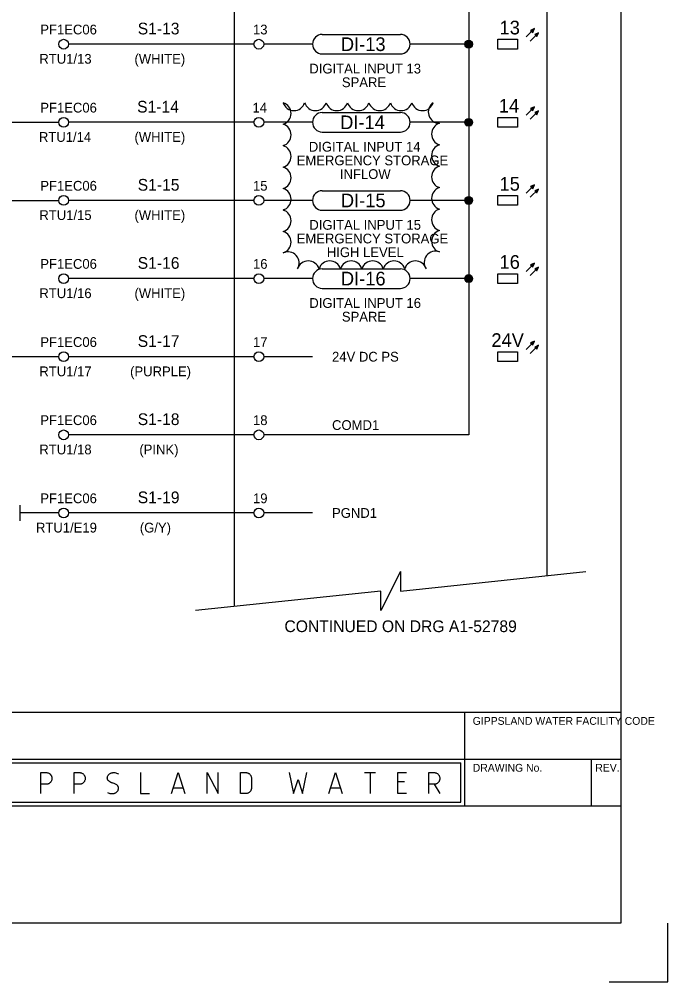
# Model space of a CAD drawing. Extents: x 0 to 841, y 0 to 594.
# Drawn here: x 674.9 to 841, y 0 to 246.4 of the extents above; entities that cross this region are included whole.
import ezdxf

# ---------------------------------------------------------------- set-up
doc = ezdxf.new("R2010")
doc.units = 0
for name, color, linetype in [('A1BORDER', 7, 'Continuous'), ('Level 1', 7, 'Continuous'), ('Level 10', 7, 'Continuous')]:
    doc.layers.add(name, color=color, linetype=linetype)

msp = doc.modelspace()

# ---------------------------------------------------------------- linework, layer by layer
at = {"layer": 'A1BORDER'}
for p, q in [((829, 581), (829, 15)), ((592.5, 69), (829, 69)), ((789, 45), (789, 69)), ((28, 57), (829, 57)), ((821.5, 45), (821.5, 57)), ((637, 56), (788, 56)), ((788, 46), (788, 56)), ((663, 46), (788, 46)), ((664, 45), (829, 45)), ((829, 15), (28, 15)), ((829, 15), (829, 15)), ((841, 0), (841, 15)), ((826, 0), (841, 0))]:
    msp.add_line(p, q, dxfattribs=at)
for points in [[(680.42, 48.16), (680.42, 53.54), (681.84, 53.54), (681.96, 53.54), (682.08, 53.52), (682.2, 53.49), (682.32, 53.45), (682.43, 53.4), (682.54, 53.34), (682.65, 53.27), (682.74, 53.19), (682.84, 53.1), (682.92, 53), (682.99, 52.9), (683.06, 52.79), (683.12, 52.67), (683.17, 52.56), (683.21, 52.43), (683.23, 52.31), (683.25, 52.18), (683.26, 52.05), (683.25, 51.91), (683.23, 51.78), (683.21, 51.66), (683.17, 51.53), (683.12, 51.42), (683.06, 51.3), (682.99, 51.19), (682.92, 51.09), (682.84, 50.99), (682.74, 50.9), (682.65, 50.82), (682.54, 50.75), (682.43, 50.69), (682.32, 50.64), (682.2, 50.6), (682.08, 50.57), (681.96, 50.55), (681.84, 50.55), (680.42, 50.55)], [(688.93, 48.16), (688.93, 53.54), (690.35, 53.54), (690.47, 53.54), (690.59, 53.52), (690.71, 53.49), (690.83, 53.45), (690.94, 53.4), (691.05, 53.34), (691.16, 53.27), (691.26, 53.19), (691.35, 53.1), (691.43, 53), (691.51, 52.9), (691.57, 52.79), (691.63, 52.67), (691.68, 52.56), (691.72, 52.43), (691.75, 52.31), (691.76, 52.18), (691.77, 52.05), (691.76, 51.91), (691.75, 51.78), (691.72, 51.66), (691.68, 51.53), (691.63, 51.42), (691.57, 51.3), (691.51, 51.19), (691.43, 51.09), (691.35, 50.99), (691.26, 50.9), (691.16, 50.82), (691.05, 50.75), (690.94, 50.69), (690.83, 50.64), (690.71, 50.6), (690.59, 50.57), (690.47, 50.55), (690.35, 50.55), (688.93, 50.55)], [(697.45, 48.46), (697.67, 48.36), (697.9, 48.27), (698.12, 48.21), (698.36, 48.17), (698.6, 48.16), (698.84, 48.16), (698.87, 48.16), (699.03, 48.18), (699.18, 48.21), (699.33, 48.26), (699.48, 48.32), (699.62, 48.4), (699.72, 48.46), (699.81, 48.53), (699.9, 48.61), (699.98, 48.69), (700.05, 48.78), (700.11, 48.88), (700.17, 48.99), (700.22, 49.09), (700.25, 49.21), (700.28, 49.32), (700.29, 49.36), (700.3, 49.44), (700.3, 49.52), (700.3, 49.61), (700.29, 49.69), (700.27, 49.77), (700.25, 49.86), (700.22, 49.93), (700.18, 50.01), (700.14, 50.09), (700.09, 50.15), (700.04, 50.21), (700.01, 50.25), (699.85, 50.39), (699.69, 50.51), (699.52, 50.61), (699.34, 50.7), (699.15, 50.78), (698.95, 50.83), (698.87, 50.85), (698.68, 50.9), (698.49, 50.96), (698.3, 51.04), (698.12, 51.14), (697.96, 51.26), (697.8, 51.39), (697.73, 51.45), (697.67, 51.51), (697.62, 51.57), (697.58, 51.64), (697.53, 51.71), (697.5, 51.79), (697.47, 51.87), (697.46, 51.95), (697.44, 52.04), (697.43, 52.12), (697.43, 52.21), (697.44, 52.29), (697.45, 52.35), (697.47, 52.46), (697.51, 52.58), (697.55, 52.69), (697.61, 52.79), (697.67, 52.89), (697.74, 52.99), (697.82, 53.07), (697.9, 53.15), (697.99, 53.23), (698.02, 53.24), (698.15, 53.33), (698.3, 53.4), (698.44, 53.45), (698.6, 53.5), (698.75, 53.52), (698.87, 53.54), (699.11, 53.55), (699.35, 53.53), (699.58, 53.49), (699.82, 53.43), (700.04, 53.35), (700.27, 53.25)], [(705.96, 53.54), (705.96, 48.16), (708.23, 48.16)], [(713.91, 48.16), (715.61, 53.54), (717.32, 48.16)], [(722.99, 48.16), (722.99, 53.54), (725.83, 48.16), (725.83, 53.54)], [(731.52, 48.16), (731.52, 53.54), (732.94, 53.54), (733.06, 53.54), (733.18, 53.52), (733.3, 53.49), (733.42, 53.45), (733.53, 53.4), (733.64, 53.34), (733.75, 53.27), (733.84, 53.19), (733.94, 53.1), (734.02, 53), (734.09, 52.9), (734.16, 52.79), (734.22, 52.67), (734.27, 52.56), (734.31, 52.43), (734.33, 52.31), (734.35, 52.18), (734.36, 52.05), (734.36, 49.66), (734.35, 49.52), (734.33, 49.39), (734.31, 49.27), (734.27, 49.14), (734.22, 49.02), (734.16, 48.91), (734.09, 48.8), (734.02, 48.7), (733.94, 48.6), (733.84, 48.51), (733.75, 48.43), (733.64, 48.36), (733.53, 48.3), (733.42, 48.25), (733.3, 48.21), (733.18, 48.18), (733.06, 48.16), (732.94, 48.16), (731.52, 48.16)], [(744.01, 53.54), (745.14, 48.16), (746.28, 51.75), (747.41, 48.16), (748.55, 53.54)], [(754.22, 48.16), (755.92, 53.54), (757.63, 48.16)], [(763.31, 53.54), (766.15, 53.54)], [(764.73, 53.54), (764.73, 48.16)], [(774.09, 48.16), (771.82, 48.16), (771.82, 53.54), (774.09, 53.54)], [(779.78, 48.16), (779.78, 53.54), (781.2, 53.54), (781.32, 53.54), (781.44, 53.52), (781.56, 53.49), (781.68, 53.45), (781.79, 53.4), (781.9, 53.34), (782.01, 53.27), (782.1, 53.19), (782.2, 53.1), (782.28, 53), (782.35, 52.9), (782.42, 52.79), (782.48, 52.67), (782.53, 52.56), (782.56, 52.43), (782.59, 52.31), (782.61, 52.18), (782.61, 52.05), (782.61, 51.91), (782.59, 51.78), (782.56, 51.66), (782.53, 51.53), (782.48, 51.42), (782.42, 51.3), (782.35, 51.19), (782.28, 51.09), (782.2, 50.99), (782.1, 50.9), (782.01, 50.82), (781.9, 50.75), (781.79, 50.69), (781.68, 50.64), (781.56, 50.6), (781.44, 50.57), (781.32, 50.55), (781.2, 50.55), (779.78, 50.55)], [(714.48, 49.66), (716.75, 49.66)], [(754.79, 49.66), (757.06, 49.66)], [(773.53, 51.15), (771.82, 51.15)], [(781.2, 50.55), (782.61, 48.16)]]:
    msp.add_lwpolyline(points, dxfattribs=at)
at = {"layer": 'Level 1'}
for p, q in [((790, 480), (790, 140)), ((752.5, 242.5), (772.5, 242.5)), ((735, 240), (687.5, 240)), ((750, 240), (737.5, 240)), ((790, 240), (775, 240)), ((752.5, 237.5), (772.5, 237.5)), ((752.5, 222.5), (772.5, 222.5)), ((280, 220), (685, 220)), ((735, 220), (687.5, 220)), ((750, 220), (737.5, 220)), ((790, 220), (775, 220)), ((752.5, 217.5), (772.5, 217.5)), ((752.5, 202.5), (772.5, 202.5)), ((280, 200), (685, 200)), ((735, 200), (687.5, 200)), ((750, 200), (737.5, 200)), ((790, 200), (775, 200)), ((752.5, 197.5), (772.5, 197.5)), ((752.5, 182.5), (772.5, 182.5)), ((735, 180), (687.5, 180)), ((750, 180), (737.5, 180)), ((790, 180), (775, 180)), ((752.5, 177.5), (772.5, 177.5)), ((685, 160), (630, 160)), ((735, 160), (687.5, 160)), ((750, 160), (737.5, 160)), ((735, 140), (687.5, 140)), ((790, 140), (737.5, 140)), ((685, 120), (675, 120)), ((735, 120), (687.5, 120)), ((750, 120), (737.5, 120)), ((772.5, 105), (767.5, 95)), ((772.5, 105), (772.5, 100)), ((772.5, 100), (820, 105)), ((767.5, 100), (720, 95)), ((767.5, 95), (767.5, 100))]:
    msp.add_line(p, q, dxfattribs=at)
msp.add_lwpolyline([(730, 96.05), (730, 560), (810, 560), (810, 103.95)], dxfattribs=at)
for points in [[(797.5, 241.25), (802.5, 241.25), (802.5, 238.75), (797.5, 238.75)], [(797.5, 221.25), (802.5, 221.25), (802.5, 218.75), (797.5, 218.75)], [(797.5, 201.25), (802.5, 201.25), (802.5, 198.75), (797.5, 198.75)], [(797.5, 181.25), (802.5, 181.25), (802.5, 178.75), (797.5, 178.75)], [(797.5, 161.25), (802.5, 161.25), (802.5, 158.75), (797.5, 158.75)]]:
    msp.add_lwpolyline(points, close=True, dxfattribs=at)
for centre, radius, start, end in [((752.5, 240), 2.5, 90, 270), ((772.5, 240), 2.5, 270, 90), ((745.24, 225.87), 2.88, 197.5, 342.5), ((741.63, 222.26), 2.88, 287.5, 72.5), ((750.73, 225.87), 2.88, 197.5, 342.5), ((756.22, 225.87), 2.88, 197.5, 342.5), ((761.71, 225.87), 2.88, 197.5, 342.5), ((767.2, 225.87), 2.88, 197.5, 342.5), ((772.69, 225.87), 2.88, 197.5, 342.5), ((778.18, 225.87), 2.88, 197.5, 342.5), ((782.54, 222.62), 2.88, 124.2101, 269.2101), ((752.5, 220), 2.5, 90, 270), ((772.5, 220), 2.5, 270, 90), ((741.63, 216.77), 2.88, 287.5, 72.5), ((783.37, 217), 2.88, 107.5, 252.5), ((741.63, 211.28), 2.88, 287.5, 72.5), ((783.37, 211.51), 2.88, 107.5, 252.5), ((741.63, 205.79), 2.88, 287.5, 72.5), ((783.37, 206.02), 2.88, 107.5, 252.5), ((741.63, 200.3), 2.88, 287.5, 72.5), ((752.5, 200), 2.5, 90, 270), ((772.5, 200), 2.5, 270, 90), ((783.37, 200.54), 2.88, 107.5, 252.5), ((741.63, 194.81), 2.88, 287.5, 72.5), ((783.37, 195.05), 2.88, 107.5, 252.5), ((783.37, 189.56), 2.88, 107.5, 252.5), ((741.63, 189.32), 2.88, 287.5, 72.5), ((743.69, 183.96), 2.88, 329.5167, 114.5167), ((781.48, 184.12), 2.88, 69.3086, 214.3086), ((748.92, 181.63), 2.88, 17.5, 162.5), ((752.5, 180), 2.5, 90, 270), ((754.41, 181.63), 2.88, 17.5, 162.5), ((759.9, 181.63), 2.88, 17.5, 162.5), ((765.39, 181.63), 2.88, 17.5, 162.5), ((770.87, 181.63), 2.88, 17.5, 162.5), ((772.5, 180), 2.5, 270, 90), ((776.36, 181.63), 2.88, 17.5, 162.5)]:
    msp.add_arc(centre, radius, start, end, dxfattribs=at)
at = {"layer": 'Level 10'}
for p, q in [((804.73, 241.86), (806.86, 243.98)), ((805.79, 240.8), (807.91, 242.92)), ((805.96, 243.58), (806.67, 243.58)), ((806, 243.43), (806.61, 243.43)), ((806.14, 243.28), (806.53, 243.28)), ((806.29, 243.72), (806.74, 243.72)), ((806.3, 243.12), (806.47, 243.12)), ((806.62, 243.88), (806.81, 243.88)), ((807.02, 242.52), (807.73, 242.52)), ((807.06, 242.37), (807.66, 242.37)), ((807.21, 242.22), (807.6, 242.22)), ((807.35, 242.66), (807.8, 242.66)), ((807.36, 242.06), (807.53, 242.06)), ((807.68, 242.81), (807.87, 242.81)), ((789.01, 240.1), (790.99, 240.1)), ((789.02, 239.8), (790.98, 239.8)), ((789.08, 240.4), (790.92, 240.4)), ((789.13, 239.5), (790.87, 239.5)), ((789.29, 240.7), (790.71, 240.7)), ((789.4, 239.2), (790.6, 239.2)), ((790, 241), (790, 241)), ((804.73, 221.86), (806.86, 223.98)), ((805.79, 220.8), (807.91, 222.92)), ((805.96, 223.58), (806.67, 223.58)), ((806, 223.43), (806.61, 223.43)), ((806.14, 223.28), (806.53, 223.28)), ((806.29, 223.72), (806.74, 223.72)), ((806.3, 223.12), (806.47, 223.12)), ((806.62, 223.88), (806.81, 223.88)), ((807.02, 222.52), (807.73, 222.52)), ((807.06, 222.37), (807.66, 222.37)), ((807.21, 222.22), (807.6, 222.22)), ((807.35, 222.66), (807.8, 222.66)), ((807.36, 222.06), (807.53, 222.06)), ((807.68, 222.81), (807.87, 222.81)), ((789.01, 220.1), (790.99, 220.1)), ((789.02, 219.8), (790.98, 219.8)), ((789.08, 220.4), (790.92, 220.4)), ((789.13, 219.5), (790.87, 219.5)), ((789.29, 220.7), (790.71, 220.7)), ((790, 221), (790, 221)), ((789.4, 219.2), (790.6, 219.2)), ((804.73, 201.86), (806.86, 203.98)), ((805.79, 200.8), (807.91, 202.92)), ((805.96, 203.58), (806.67, 203.58)), ((806, 203.43), (806.61, 203.43)), ((806.14, 203.28), (806.53, 203.28)), ((806.29, 203.72), (806.74, 203.72)), ((806.3, 203.12), (806.47, 203.12)), ((806.62, 203.88), (806.81, 203.88)), ((807.02, 202.52), (807.73, 202.52)), ((807.06, 202.37), (807.66, 202.37)), ((807.21, 202.22), (807.6, 202.22)), ((807.35, 202.66), (807.8, 202.66)), ((807.36, 202.06), (807.53, 202.06)), ((807.68, 202.81), (807.87, 202.81)), ((789.01, 200.1), (790.99, 200.1)), ((789.02, 199.8), (790.98, 199.8)), ((789.08, 200.4), (790.92, 200.4)), ((789.29, 200.7), (790.71, 200.7)), ((790, 201), (790, 201)), ((789.13, 199.5), (790.87, 199.5)), ((789.4, 199.2), (790.6, 199.2)), ((804.73, 181.85), (806.86, 183.98)), ((805.79, 180.8), (807.91, 182.92)), ((805.96, 183.58), (806.67, 183.58)), ((806, 183.43), (806.61, 183.43)), ((806.14, 183.28), (806.53, 183.28)), ((806.29, 183.72), (806.74, 183.72)), ((806.3, 183.12), (806.47, 183.12)), ((806.62, 183.88), (806.81, 183.88)), ((807.02, 182.52), (807.73, 182.52)), ((807.06, 182.37), (807.66, 182.37)), ((807.35, 182.66), (807.8, 182.66)), ((807.68, 182.81), (807.87, 182.81)), ((789.01, 180.1), (790.99, 180.1)), ((789.08, 180.4), (790.92, 180.4)), ((789.29, 180.7), (790.71, 180.7)), ((790, 181), (790, 181)), ((807.21, 182.22), (807.6, 182.22)), ((807.36, 182.06), (807.53, 182.06)), ((789.02, 179.8), (790.98, 179.8)), ((789.13, 179.5), (790.87, 179.5)), ((789.4, 179.2), (790.6, 179.2)), ((804.73, 161.85), (806.86, 163.98)), ((805.79, 160.8), (807.91, 162.92)), ((805.96, 163.58), (806.67, 163.58)), ((806, 163.43), (806.61, 163.43)), ((806.14, 163.28), (806.53, 163.28)), ((806.29, 163.72), (806.74, 163.72)), ((806.3, 163.12), (806.47, 163.12)), ((806.62, 163.88), (806.81, 163.88)), ((807.35, 162.66), (807.8, 162.66)), ((807.68, 162.81), (807.87, 162.81)), ((807.02, 162.52), (807.73, 162.52)), ((807.06, 162.37), (807.66, 162.37)), ((807.21, 162.22), (807.6, 162.22)), ((807.36, 162.06), (807.53, 162.06)), ((675, 122), (675, 118))]:
    msp.add_line(p, q, dxfattribs=at)
for points in [[(806.86, 243.98), (805.88, 243.54), (806.41, 243)], [(807.91, 242.92), (806.94, 242.48), (807.48, 241.94)], [(806.86, 223.98), (805.88, 223.54), (806.41, 223)], [(807.91, 222.92), (806.94, 222.48), (807.48, 221.94)], [(806.86, 203.98), (805.88, 203.54), (806.41, 203)], [(807.91, 202.92), (806.94, 202.48), (807.48, 201.94)], [(806.86, 183.98), (805.88, 183.54), (806.41, 183)], [(807.91, 182.92), (806.94, 182.48), (807.48, 181.94)], [(806.86, 163.98), (805.88, 163.54), (806.41, 163)], [(807.91, 162.92), (806.94, 162.48), (807.48, 161.94)]]:
    msp.add_lwpolyline(points, close=True, dxfattribs=at)
for centre, radius in [((686.25, 240), 1.25), ((736.25, 240), 1.25), ((790, 240), 1), ((686.25, 220), 1.25), ((736.25, 220), 1.25), ((790, 220), 1), ((686.25, 200), 1.25), ((736.25, 200), 1.25), ((790, 200), 1), ((686.25, 180), 1.25), ((736.25, 180), 1.25), ((790, 180), 1), ((686.25, 160), 1.25), ((736.25, 160), 1.25), ((686.25, 140), 1.25), ((736.25, 140), 1.25), ((686.25, 120), 1.25), ((736.25, 120), 1.25)]:
    msp.add_circle(centre, radius, dxfattribs=at)

# ---------------------------------------------------------------- texts
at = {"layer": 'A1BORDER'}
for s, p in [('GIPPSLAND WATER FACILITY CODE', (791.03, 65.77)), ('DRAWING No.', (791.03, 53.77)), ('REV.', (822.43, 53.77))]:
    msp.add_text(s, height=2, dxfattribs=at).set_placement(p)
at = {"layer": 'Level 1'}
for s, height, p in [('PF1EC06', 2.5, (680.27, 242.5)), ('S1-13', 3, (705.22, 242.5)), ('13', 2.5, (734.75, 242.5)), ('13', 3.5, (797.91, 242.5)), ('DI-13', 3.5, (757.27, 238.25)), ('RTU1/13', 2.5, (680.03, 235)), ('(WHITE)', 2.5, (704.39, 235)), ('DIGITAL INPUT 13', 2.5, (749.18, 232.5)), ('SPARE', 2.5, (757.52, 229)), ('PF1EC06', 2.5, (680.27, 222.5)), ('S1-14', 3, (705.07, 222.5)), ('14', 2.5, (734.63, 222.5)), ('14', 3.5, (797.73, 222.5)), ('DI-14', 3.5, (757.09, 218.25)), ('RTU1/14', 2.5, (679.91, 215)), ('(WHITE)', 2.5, (704.39, 215)), ('DIGITAL INPUT 14', 2.5, (749.05, 212.5)), ('EMERGENCY STORAGE', 2.5, (745.94, 209)), ('INFLOW', 2.5, (757.02, 205.5)), ('PF1EC06', 2.5, (680.27, 202.5)), ('S1-15', 3, (705.22, 202.5)), ('15', 2.5, (734.75, 202.5)), ('15', 3.5, (797.91, 202.5)), ('DI-15', 3.5, (757.27, 198.25)), ('RTU1/15', 2.5, (680.03, 195)), ('(WHITE)', 2.5, (704.39, 195)), ('DIGITAL INPUT 15', 2.5, (749.18, 192.5)), ('EMERGENCY STORAGE', 2.5, (745.94, 189)), ('HIGH LEVEL', 2.5, (753.66, 185.5)), ('PF1EC06', 2.5, (680.27, 182.5)), ('S1-16', 3, (705.22, 182.5)), ('16', 2.5, (734.75, 182.5)), ('16', 3.5, (797.91, 182.5)), ('DI-16', 3.5, (757.27, 178.25)), ('RTU1/16', 2.5, (680.03, 175)), ('(WHITE)', 2.5, (704.39, 175)), ('DIGITAL INPUT 16', 2.5, (749.18, 172.5)), ('SPARE', 2.5, (757.52, 169)), ('S1-17', 3, (705.22, 162.5)), ('24V', 3.5, (795.82, 162.5)), ('PF1EC06', 2.5, (680.27, 162.5)), ('17', 2.5, (734.75, 162.5)), ('24V DC PS', 2.5, (755, 158.75)), ('RTU1/17', 2.5, (680.03, 155)), ('(PURPLE)', 2.5, (703.27, 155)), ('S1-18', 3, (705.22, 142.5)), ('PF1EC06', 2.5, (680.27, 142.5)), ('18', 2.5, (734.75, 142.5)), ('COMD1', 2.5, (755, 141.25)), ('RTU1/18', 2.5, (680.03, 135)), ('(PINK)', 2.5, (705.64, 135)), ('PF1EC06', 2.5, (680.27, 122.5)), ('S1-19', 3, (705.23, 122.5)), ('19', 2.5, (734.75, 122.5)), ('PGND1', 2.5, (755, 118.75)), ('RTU1/E19', 2.5, (679.16, 115)), ('(G/Y)', 2.5, (705.76, 115)), ('CONTINUED ON DRG A1-52789', 3, (742.81, 89.5))]:
    msp.add_text(s, height=height, dxfattribs=at).set_placement(p)

doc.saveas('drawing.dxf')
